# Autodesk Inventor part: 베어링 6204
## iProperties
IsCustomPart: 0
Created: 2009-02
Part Number: 베어링 6204
Material: 강, 연강
Description: 깊은 그루브 볼 베어링
Document SubType Name: Modeling
Standard: KS B 2023
Designer: KYOUNG IL JANG
Standards Organization: KS
Language: ko-KR
Size Designation: 6204 - 20 x 47 x 14
Categories: <MemberInstance><Categories><Category DisplayName="샤프트 부품" InternalName="7f7aeb1f-a693-4053-b835-cee3144e0d98" Mnemonic="SHFT"><Category DisplayName="베어링" Inter
Density: 7.86 g/cm^3
Mass: 104.255 g
Surface Area: 87.8912 cm^2
Volume: 13.264 cm^3
Author: KYOUNG IL JANG
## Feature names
1. IDS_ARRAYBALL[SIMPL:T] [Circular Pattern]
